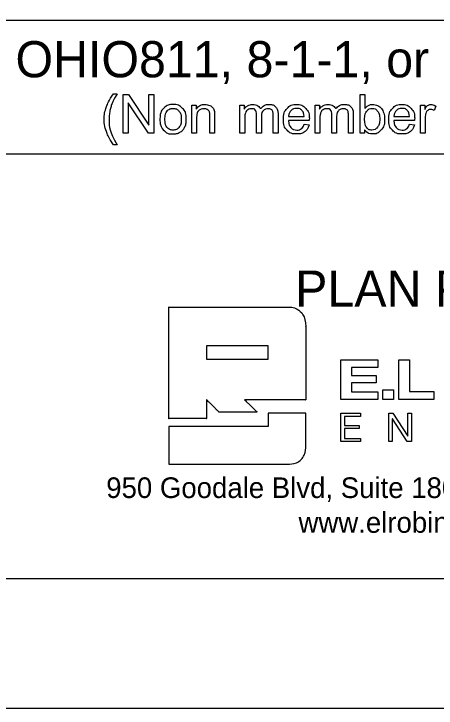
# Model space of a CAD drawing. Extents: x 0 to 34, y -4 to 22.
# Drawn here: x 3.016 to 4.651, y 0 to 2.686 of the extents above; entities that cross this region are included whole.
import ezdxf

# ---------------------------------------------------------------- set-up
doc = ezdxf.new("R2010")
doc.units = 0
for name, color, linetype in [('SH_Border', 7, 'Continuous'), ('SH_Cut_Line', 7, 'Continuous'), ('SH_Data', 7, 'Continuous'), ('SH_Text', 7, 'Continuous')]:
    doc.layers.add(name, color=color, linetype=linetype)

msp = doc.modelspace()

# ---------------------------------------------------------------- linework, layer by layer
at = {"layer": 'SH_Border'}
msp.add_lwpolyline([(1.5, 21.5), (33.5, 21.5), (33.5, 0.5), (1.5, 0.5)], close=True, dxfattribs=at)
at = {"layer": 'SH_Cut_Line'}
msp.add_lwpolyline([(0, 0), (34, 0), (34, 22), (0, 22)], close=True, dxfattribs=at)
at = {"layer": 'SH_Data'}
for p, q in [((7.2275, 2.6607), (2.9775, 2.6607)), ((7.2275, 2.1428), (2.9775, 2.1428)), ((4.0002, 1.4013), (3.7623, 1.4013)), ((3.7623, 1.4013), (3.7623, 1.3496)), ((4.0002, 1.3496), (4.0002, 1.4013)), ((3.7623, 1.3496), (4.0002, 1.3496))]:
    msp.add_line(p, q, dxfattribs=at)
for points in [[(4.282, 1.3475), (4.4248, 1.3475), (4.4248, 1.3184), (4.3235, 1.3184), (4.3235, 1.2867), (4.4196, 1.2867), (4.4196, 1.2589), (4.3235, 1.2589), (4.3235, 1.2238), (4.4256, 1.2238), (4.4256, 1.1947), (4.282, 1.1947), (4.282, 1.3475)], [(4.5071, 1.3475), (4.5486, 1.3475), (4.5486, 1.225), (4.6418, 1.225), (4.6418, 1.1947), (4.5071, 1.1947), (4.5071, 1.3475)], [(4.4444, 1.231), (4.4859, 1.231), (4.4859, 1.1947), (4.4444, 1.1947), (4.4444, 1.231)], [(4.2816, 1.1412), (4.3577, 1.1412), (4.3577, 1.1289), (4.2963, 1.1289), (4.2963, 1.0939), (4.3536, 1.0939), (4.3536, 1.0815), (4.2963, 1.0815), (4.2963, 1.0434), (4.3582, 1.0434), (4.3582, 1.031), (4.2816, 1.031), (4.2816, 1.1412)], [(4.4674, 1.1412), (4.483, 1.1412), (4.541, 1.0519), (4.5413, 1.0519), (4.5413, 1.1412), (4.5552, 1.1412), (4.5552, 1.031), (4.5392, 1.031), (4.4816, 1.1195), (4.4813, 1.1195), (4.4813, 1.031), (4.4674, 1.031), (4.4674, 1.1412)]]:
    msp.add_lwpolyline(points, dxfattribs=at)
for points, degree in [([(3.6165, 1.1201), (3.6165, 1.1222), (3.6165, 1.5497), (3.6165, 1.5518)], 2), ([(3.6165, 1.5518), (3.6187, 1.5518), (4.0679, 1.5518), (4.0701, 1.5518), (4.112, 1.5518), (4.146, 1.5178), (4.146, 1.4758)], 3), ([(4.146, 1.4758), (4.146, 1.4745), (4.146, 1.1945), (4.146, 1.1931)], 2), ([(3.8099, 1.1455), (3.8097, 1.1457), (3.7625, 1.1929), (3.7623, 1.1931)], 2), ([(3.7623, 1.1931), (3.7623, 1.1928), (3.7623, 1.1205), (3.7623, 1.1201)], 2), ([(4.146, 1.1931), (4.1448, 1.1931), (3.91, 1.1931), (3.9089, 1.1931)], 2), ([(3.9089, 1.1931), (3.9091, 1.1929), (3.9577, 1.1457), (3.9579, 1.1455)], 2), ([(4.0002, 1.1415), (4.0002, 1.1415), (4.146, 1.1415), (4.146, 1.1415), (4.146, 1.1415), (4.146, 1.0199), (4.146, 1.0199), (4.146, 0.9779), (4.112, 0.9439), (4.0701, 0.9439), (4.0701, 0.9439), (3.6165, 0.9439), (3.6165, 0.9439), (3.6165, 0.9439), (3.6165, 1.0898), (3.6165, 1.0898), (3.6165, 1.0898), (4.0002, 1.0898), (4.0002, 1.0898), (4.0002, 1.0898), (4.0002, 1.1415), (4.0002, 1.1415)], 3), ([(3.9579, 1.1455), (3.9572, 1.1455), (3.8107, 1.1455), (3.8099, 1.1455)], 2), ([(3.7623, 1.1201), (3.7616, 1.1201), (3.6172, 1.1201), (3.6165, 1.1201)], 2)]:
    msp.add_open_spline(points, degree=degree, dxfattribs=at)
at = {"layer": 'SH_Text'}
for points in [[(3.4021, 2.3766), (3.4153, 2.3766)], [(3.4389, 2.2239), (3.4389, 2.3741), (3.4592, 2.3741), (3.5382, 2.2561), (3.5382, 2.3741), (3.5572, 2.3741), (3.5572, 2.2239), (3.5369, 2.2239), (3.4579, 2.3419), (3.4579, 2.2239), (3.4389, 2.2239)], [(4.3743, 2.2239), (4.3573, 2.2239), (4.3573, 2.3741), (4.3757, 2.3741), (4.3757, 2.3206)], [(3.7048, 2.2239), (3.7048, 2.3328), (3.7214, 2.3328), (3.7214, 2.3173)], [(3.8912, 2.2239), (3.8912, 2.3328), (3.9077, 2.3328), (3.9077, 2.3174)], [(4.1826, 2.2239), (4.1826, 2.3328), (4.1991, 2.3328), (4.1991, 2.3174)], [(4.5904, 2.2239), (4.5904, 2.3328), (4.607, 2.3328), (4.607, 2.3163)], [(4.6495, 2.3293), (4.643, 2.3122)], [(3.7233, 2.2833), (3.7233, 2.2239), (3.7048, 2.2239)], [(3.7932, 2.2908), (3.7932, 2.2239), (3.7748, 2.2239), (3.7748, 2.2901)], [(3.9743, 2.2871), (3.9743, 2.2239), (3.9559, 2.2239), (3.9559, 2.2946)], [(4.0388, 2.2986), (4.0388, 2.2239), (4.0203, 2.2239), (4.0203, 2.2924)], [(4.0799, 2.2887), (4.1406, 2.2887)], [(4.2657, 2.2871), (4.2657, 2.2239), (4.2473, 2.2239), (4.2473, 2.2946)], [(4.3301, 2.2986), (4.3301, 2.2239), (4.3117, 2.2239), (4.3117, 2.2924)], [(4.4879, 2.2887), (4.5486, 2.2887)], [(3.9097, 2.2803), (3.9097, 2.2239), (3.8912, 2.2239)], [(4.16, 2.2736), (4.0788, 2.2736)], [(4.1404, 2.2591), (4.1595, 2.2567)], [(4.201, 2.2803), (4.201, 2.2239), (4.1826, 2.2239)], [(4.568, 2.2736), (4.4868, 2.2736)], [(4.5484, 2.2591), (4.5675, 2.2567)], [(4.6088, 2.2809), (4.6088, 2.2239), (4.5904, 2.2239)], [(4.3743, 2.2375), (4.3743, 2.2239)], [(3.4153, 2.1798), (3.4021, 2.1798)]]:
    msp.add_lwpolyline(points, dxfattribs=at)
for points in [[(3.4021, 2.1798), (3.3869, 2.199), (3.3763, 2.2248), (3.3657, 2.2506), (3.3657, 2.2783), (3.3657, 2.3026), (3.3736, 2.325), (3.3829, 2.3509), (3.4021, 2.3766)], [(3.4153, 2.3766), (3.4029, 2.3553), (3.3989, 2.3462), (3.3927, 2.332), (3.3891, 2.3167), (3.3847, 2.2975), (3.3847, 2.2782), (3.3847, 2.2289), (3.4153, 2.1798)], [(3.5814, 2.2783), (3.5814, 2.3085), (3.5981, 2.3231), (3.6122, 2.3352), (3.6323, 2.3352), (3.6547, 2.3352), (3.669, 2.3205), (3.6832, 2.3058), (3.6832, 2.2799), (3.6832, 2.2589), (3.6769, 2.2469), (3.6706, 2.2348), (3.6586, 2.2282), (3.6466, 2.2215), (3.6323, 2.2215), (3.6095, 2.2215), (3.5954, 2.2362), (3.5814, 2.2508), (3.5814, 2.2783)], [(3.6003, 2.2783), (3.6003, 2.2574), (3.6094, 2.247), (3.6185, 2.2366), (3.6323, 2.2366), (3.646, 2.2366), (3.6551, 2.2471), (3.6642, 2.2575), (3.6642, 2.279), (3.6642, 2.2991), (3.6551, 2.3095), (3.6459, 2.3199), (3.6323, 2.3199), (3.6185, 2.3199), (3.6094, 2.3096), (3.6003, 2.2992), (3.6003, 2.2783)], [(3.7214, 2.3173), (3.7334, 2.3352), (3.756, 2.3352), (3.7659, 2.3352), (3.7741, 2.3316), (3.7823, 2.3281), (3.7864, 2.3224), (3.7905, 2.3166), (3.7922, 2.3087), (3.7932, 2.3036), (3.7932, 2.2908)], [(3.7748, 2.2901), (3.7748, 2.3013), (3.7726, 2.3069), (3.7705, 2.3125), (3.765, 2.3158), (3.7595, 2.3191), (3.7521, 2.3191), (3.7404, 2.3191), (3.7318, 2.3117), (3.7233, 2.3042), (3.7233, 2.2833)], [(3.9077, 2.3174), (3.9128, 2.3254), (3.9214, 2.3303), (3.9299, 2.3352), (3.9407, 2.3352), (3.9528, 2.3352), (3.9606, 2.3301), (3.9683, 2.3251), (3.9715, 2.3161), (3.9844, 2.3352), (4.0051, 2.3352), (4.0213, 2.3352), (4.03, 2.3262), (4.0388, 2.3172), (4.0388, 2.2986)], [(3.9559, 2.2946), (3.9559, 2.3069), (3.9514, 2.313), (3.9469, 2.3191), (3.9366, 2.3191), (3.9288, 2.3191), (3.9222, 2.315), (3.9156, 2.311), (3.9126, 2.3031), (3.9097, 2.2952), (3.9097, 2.2803)], [(4.0203, 2.2924), (4.0203, 2.3035), (4.0185, 2.3083), (4.0168, 2.3132), (4.012, 2.3162), (4.0073, 2.3191), (4.001, 2.3191), (3.9895, 2.3191), (3.9819, 2.3115), (3.9743, 2.3039), (3.9743, 2.2871)], [(4.1595, 2.2567), (4.155, 2.24), (4.1428, 2.2307), (4.1306, 2.2215), (4.1117, 2.2215), (4.0878, 2.2215), (4.0738, 2.2362), (4.0598, 2.2509), (4.0598, 2.2774), (4.0598, 2.3049), (4.074, 2.32), (4.0881, 2.3352), (4.1106, 2.3352), (4.1324, 2.3352), (4.1463, 2.3203), (4.1601, 2.3055), (4.1601, 2.2785), (4.1601, 2.2769), (4.16, 2.2736)], [(4.1406, 2.2887), (4.1394, 2.3025), (4.1337, 2.3094), (4.1249, 2.3201), (4.1108, 2.3201), (4.0981, 2.3201), (4.0894, 2.3115), (4.0808, 2.303), (4.0799, 2.2887)], [(4.1991, 2.3174), (4.2042, 2.3254), (4.2127, 2.3303), (4.2212, 2.3352), (4.2321, 2.3352), (4.2442, 2.3352), (4.2519, 2.3301), (4.2597, 2.3251), (4.2628, 2.3161), (4.2758, 2.3352), (4.2965, 2.3352), (4.3127, 2.3352), (4.3214, 2.3262), (4.3301, 2.3172), (4.3301, 2.2986)], [(4.2473, 2.2946), (4.2473, 2.3069), (4.2428, 2.313), (4.2383, 2.3191), (4.228, 2.3191), (4.2202, 2.3191), (4.2136, 2.315), (4.207, 2.311), (4.204, 2.3031), (4.201, 2.2952), (4.201, 2.2803)], [(4.3117, 2.2924), (4.3117, 2.3035), (4.3099, 2.3083), (4.3081, 2.3132), (4.3034, 2.3162), (4.2987, 2.3191), (4.2923, 2.3191), (4.2809, 2.3191), (4.2733, 2.3115), (4.2657, 2.3039), (4.2657, 2.2871)], [(4.3741, 2.2792), (4.3741, 2.2596), (4.3794, 2.2509), (4.3881, 2.2366), (4.4029, 2.2366), (4.415, 2.2366), (4.4238, 2.2471), (4.4326, 2.2576), (4.4326, 2.2784), (4.4326, 2.2998), (4.4241, 2.3099), (4.4157, 2.3201), (4.4038, 2.3201), (4.3917, 2.3201), (4.3829, 2.3096), (4.3741, 2.299), (4.3741, 2.2792)], [(4.3757, 2.3206), (4.3874, 2.3352), (4.4055, 2.3352), (4.4155, 2.3352), (4.4245, 2.3311), (4.4335, 2.3271), (4.4392, 2.3198), (4.445, 2.3124), (4.4483, 2.3021), (4.4516, 2.2918), (4.4516, 2.28), (4.4516, 2.252), (4.4378, 2.2368), (4.4239, 2.2215), (4.4046, 2.2215), (4.3853, 2.2215), (4.3743, 2.2375)], [(4.5675, 2.2567), (4.563, 2.24), (4.5508, 2.2307), (4.5386, 2.2215), (4.5196, 2.2215), (4.4958, 2.2215), (4.4818, 2.2362), (4.4678, 2.2509), (4.4678, 2.2774), (4.4678, 2.3049), (4.482, 2.32), (4.4961, 2.3352), (4.5186, 2.3352), (4.5404, 2.3352), (4.5543, 2.3203), (4.5681, 2.3055), (4.5681, 2.2785), (4.5681, 2.2769), (4.568, 2.2736)], [(4.5486, 2.2887), (4.5474, 2.3025), (4.5417, 2.3094), (4.5328, 2.3201), (4.5188, 2.3201), (4.5061, 2.3201), (4.4974, 2.3115), (4.4888, 2.303), (4.4879, 2.2887)], [(4.607, 2.3163), (4.6133, 2.3278), (4.6187, 2.3315), (4.6241, 2.3352), (4.6305, 2.3352), (4.6398, 2.3352), (4.6495, 2.3293)], [(4.643, 2.3122), (4.6363, 2.3162), (4.6295, 2.3162), (4.6235, 2.3162), (4.6187, 2.3125), (4.6139, 2.3089), (4.6119, 2.3024), (4.6088, 2.2926), (4.6088, 2.2809)], [(4.0788, 2.2736), (4.0799, 2.2557), (4.089, 2.2462), (4.0981, 2.2366), (4.1117, 2.2366), (4.1219, 2.2366), (4.1291, 2.242), (4.1362, 2.2473), (4.1404, 2.2591)], [(4.4868, 2.2736), (4.4879, 2.2557), (4.497, 2.2462), (4.5061, 2.2366), (4.5197, 2.2366), (4.5299, 2.2366), (4.537, 2.242), (4.5442, 2.2473), (4.5484, 2.2591)]]:
    msp.add_open_spline(points, degree=3, dxfattribs=at)

# ---------------------------------------------------------------- texts
at = {"layer": 'SH_Data'}
for s, p in [('950 Goodale Blvd, Suite 180 · Grandview Heights, Ohio 43212', (3.3734, 0.8129)), ('www.elrobinsonengineering.com', (4.1181, 0.6784))]:
    msp.add_text(s, height=0.079861, rotation=360, dxfattribs=at).set_placement(p)
at = {"layer": 'SH_Text'}
for s, p in [('OHIO811, 8-1-1, or 1-800-362-2764', (3.022, 2.4406)), ('PLAN PREPARED BY:', (4.1053, 1.553))]:
    msp.add_text(s, height=0.14, dxfattribs=at).set_placement(p)

doc.saveas('drawing.dxf')
